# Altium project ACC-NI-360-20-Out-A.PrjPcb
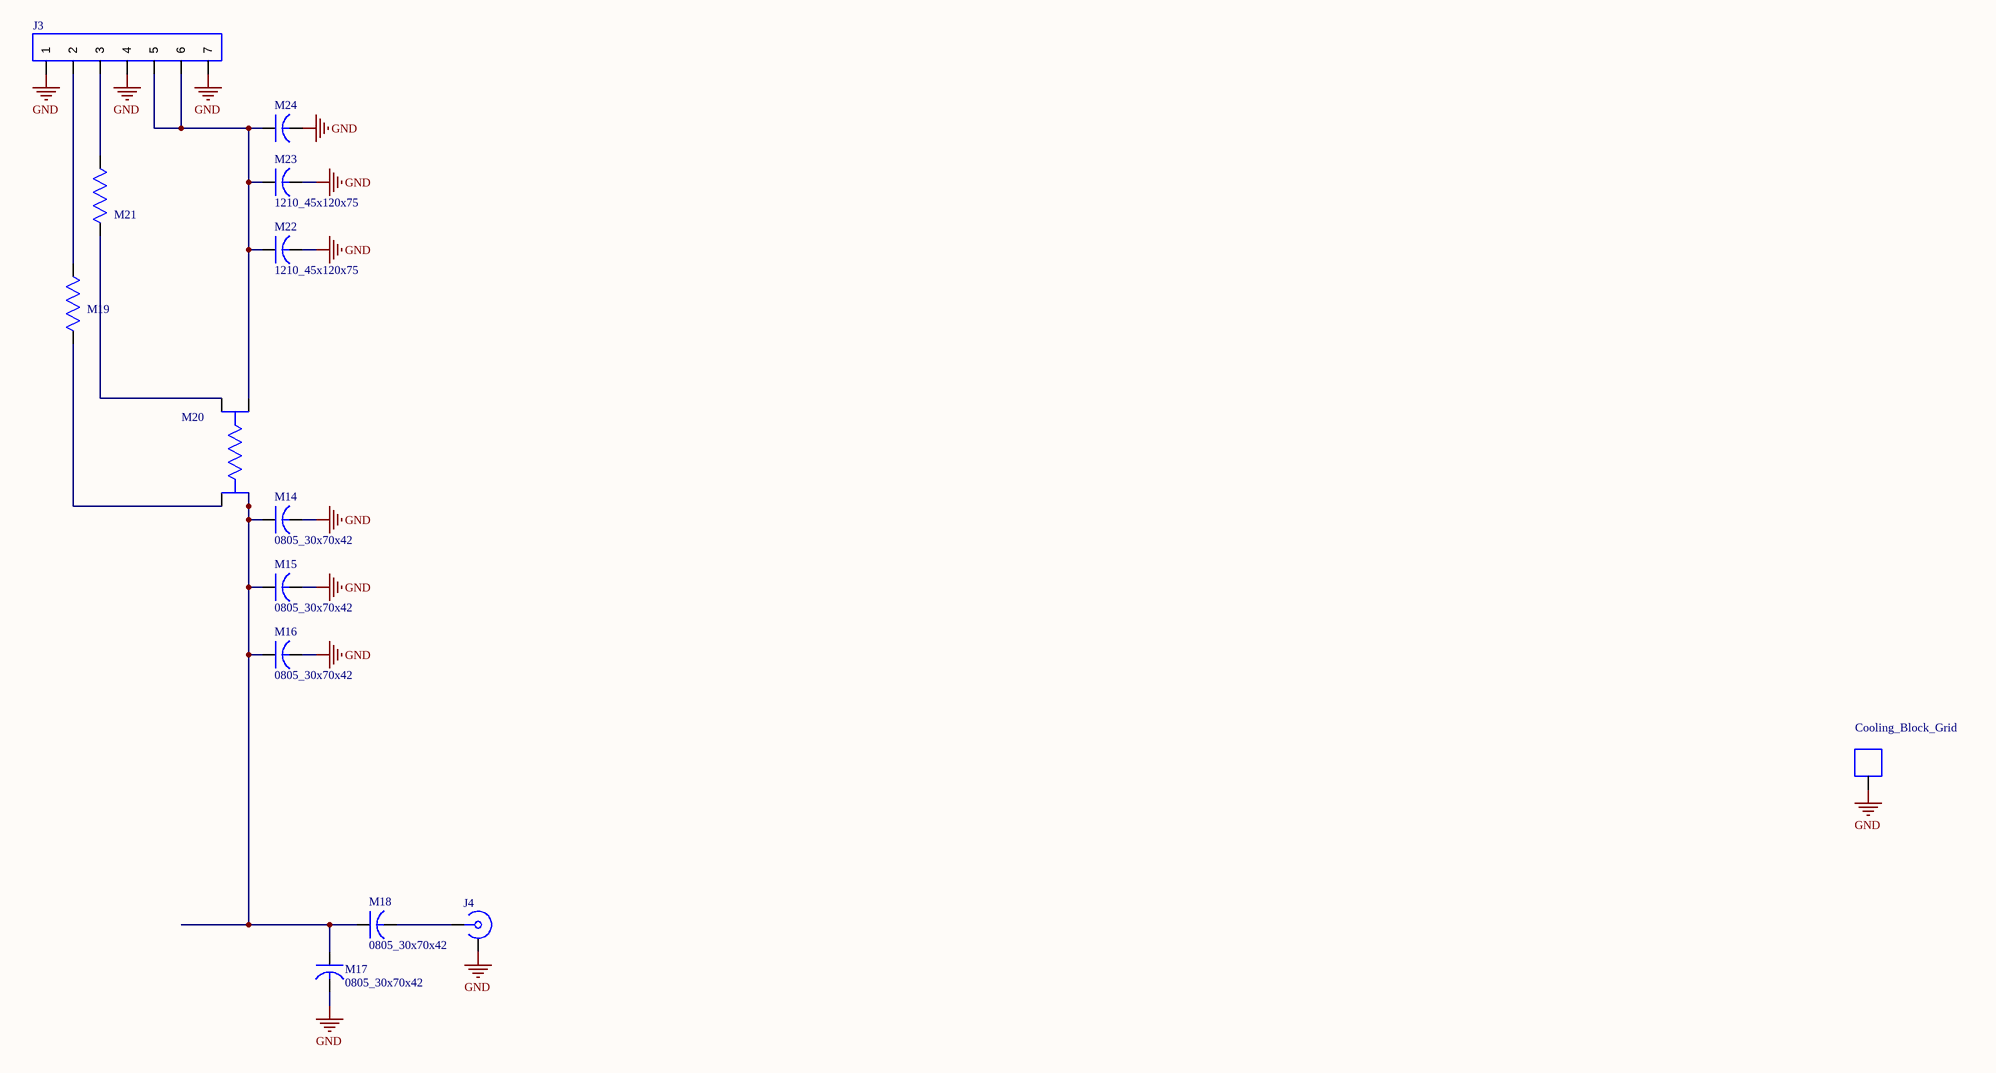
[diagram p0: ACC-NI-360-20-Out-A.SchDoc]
Description: Layout updates; Modified From: DFN6-15-34-A (Eagle)
1 sheet, 14 parts. Net scope: global (net labels, ports and power ports of the same name join across sheets).
Board file: ACC-NI-360-20-Out-A.PcbDoc

## Sheet ACC-NI-360-20-Out-A.SchDoc
size 609 x 419 mm; Revision: A; SheetNumber: 1; SheetTotal: 1

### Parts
H2  Cooling_Block_Grid  [Cooling_Block_Grid]
J3  Header_H_7-Pin_100mil  [Header_H_7-Pin_100mil]  (value not drawn)
J4  SMA Panel Mount_RevB  [SMA Panel Mount_RevB]  (value not drawn)
M14  0805_30x70x42  [0805_30x70x42]
M15  0805_30x70x42  [0805_30x70x42]
M16  0805_30x70x42  [0805_30x70x42]
M17  0805_30x70x42  [0805_30x70x42]
M18  0805_30x70x42  [0805_30x70x42]
M19  0402_26x26x20  [0402_26x26x20]  (value not drawn)
M20  Ohmite_LVK12  [Ohmite_LVK12]  (value not drawn)
M21  0402_26x26x20  [0402_26x26x20]  (value not drawn)
M22  1210_45x120x75  [1210_45x120x75]
M23  1210_45x120x75  [1210_45x120x75]
M24  Panasonic_K-Size  [Panasonic_K-Size]  (value not drawn)

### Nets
GND: H2.1 J3.1 J3.4 J3.7 J4.2 M14.1 M15.1 M16.1 M17.1 M22.1 M23.1 M24.1
NetJ3_2: J3.2 M19.2
NetJ3_3: J3.3 M21.2
NetJ3_5: J3.5 J3.6 M20.4 M22.2 M23.2 M24.2
NetJ4_1: J4.1 M18.1
NetM14_2: M14.2 M15.2 M16.2 M17.2 M18.2 M20.3
NetM19_1: M19.1 M20.2
NetM20_1: M20.1 M21.1

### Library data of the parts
H2 = Mounting Holes
J3 = Header_7-Pin: Header 7-Pin
J4 = RF_Conn
M14-M18 M22-M24 = Capacitor
M19 M21 = Resistor
M20 = Resistor_Ohmite_Current_Sense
